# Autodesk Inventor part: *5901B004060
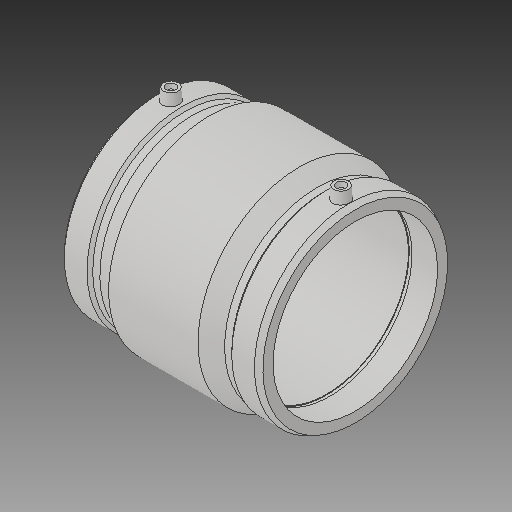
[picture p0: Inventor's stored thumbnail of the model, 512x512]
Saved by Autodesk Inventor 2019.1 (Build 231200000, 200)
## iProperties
Created: 2017-06
Part Number: *5901B004060
Material: Generic
Description: PLASSON IPS COUPLER 6''
Document SubType Name: Modeling
Designer: KIM
Mass: 8622.19 g
Surface Area: 6772.47 cm^2
Volume: 8622.19 cm^3
Density: 1 g/cm^3
Appearance: Default
Author: KIM
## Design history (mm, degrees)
derived "5901B.ipt"
feature "Solid1::5901B.ipt"
tag "TaggingFeature1"
body "Solid1"
other parameters: "d0" = 202.946, "d1" = 168, "d2" = 207.01, "d3" = 100.076, "d4" = 50.7365, "d5" = 186.309, "d6" = 134.4, "d7" = 168, "d8" = 168 deg, "d10" = 40.0304, "d11" = 13.34347, "d13" = 202.946, "d14" = 17.6296, "d18" = 168, "d19" = 3.52592, "d20" = 168 deg, "d22" = 194.5894, "d23" = 207.01, "d24" = 188.75172, "d25" = 135 deg, "d26" = 91.3257, "d27" = 135 deg, "d29" = 108.712, "d30" = 15, "d31" = 71.0311, "d34" = 5 deg, "d35" = 15, "d39" = 5 deg, "d41" = 4, "d42" = 14, "d43" = 0, "d45" = 4, "d46" = 14, "d47" = 0, "d48" = 3, "d49" = 0, "d50" = 3, "d51" = 0, "d52" = 29.02204, "d53" = 7.25551, "d55" = 100.076, "d_" = 168, "L_" = 202.946, "L_1" = 100.076, "D_" = 207.01, "A_" = 108.712, "d_2" = 12, "B_" = 108.712
